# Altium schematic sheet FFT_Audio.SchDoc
size A; Organization: Altium Limited; Address1: L3, 12a Rodborough Rd; Address2: Frenchs Forest; Address3: NSW; Address4: Australia 2086; DocumentNumber: 1; SheetNumber: 1; SheetTotal: 1
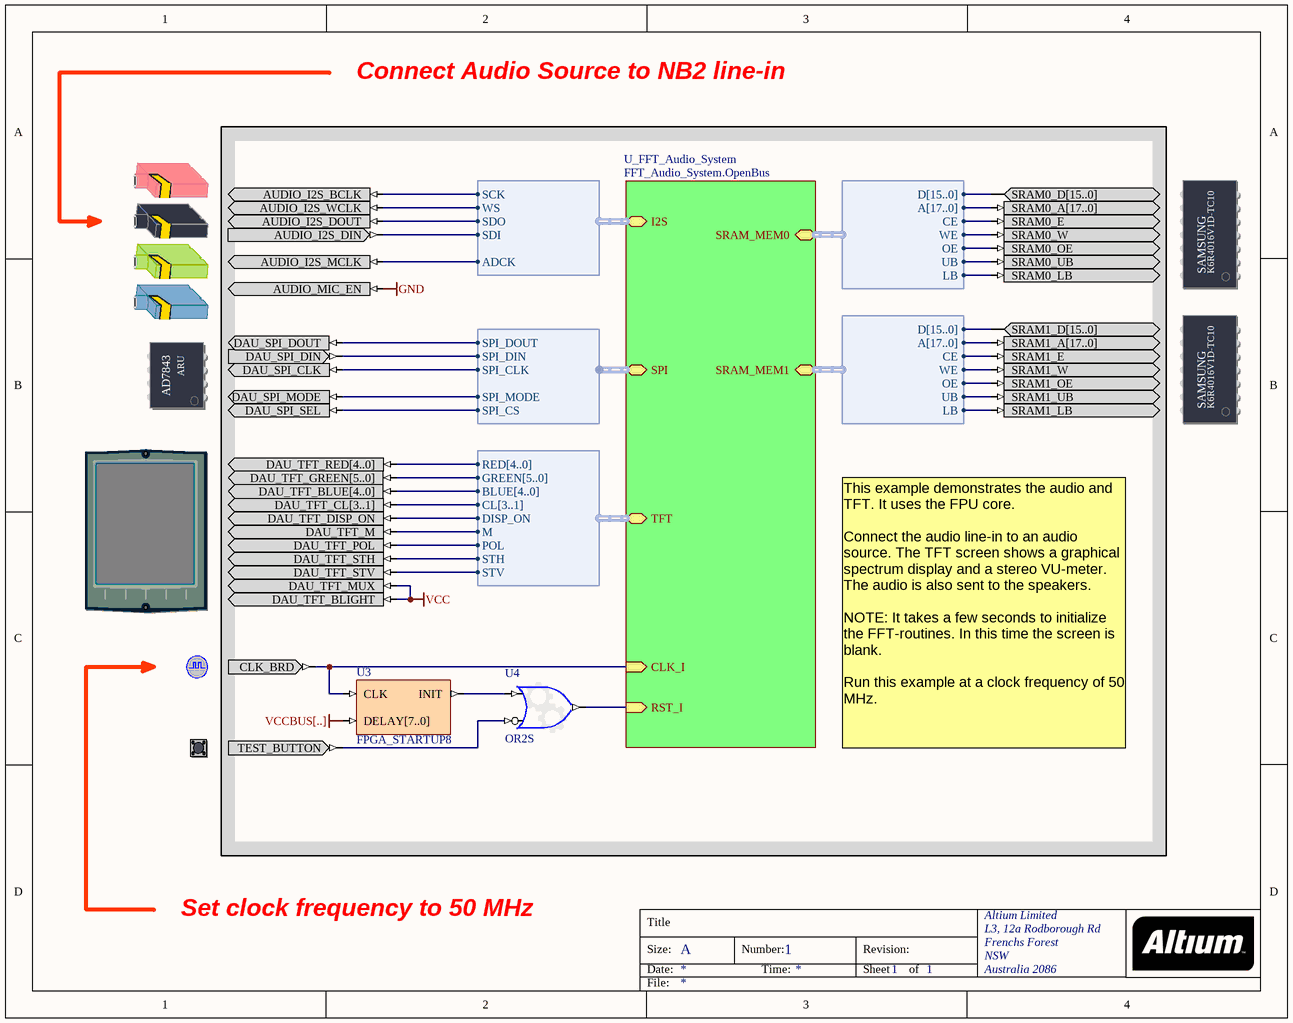
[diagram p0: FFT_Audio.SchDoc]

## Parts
(Parts that share a designator on the sheet are numbered #1, #2 ... from top to bottom, then left to right.)
?#1  AUDIO_CODEC  (value not drawn)
?#2  SRAM_DAUGHTER0  (value not drawn)
?#3  SRAM_DAUGHTER1  (value not drawn)
?#4  TOUCH_SCREEN_DIGITIZER  (value not drawn)
?#5  TFT_LCD  (value not drawn)
?#6  CLOCK_BOARD  (value not drawn)
?#7  TEST_BUTTON  (value not drawn)
U3  FPGA_STARTUP8
U4  OR2S

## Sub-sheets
U_FFT_Audio_System = FFT_Audio_System.OpenBus: RST_I (in), CLK_I (in), SPI (harness SPI_W_NB), I2S (harness I2S_W_Both), TFT (harness VGA32_TFT), SRAM_MEM0 (harness WB_MEM_CTRL_SRAM16_A18), SRAM_MEM1 (harness WB_MEM_CTRL_SRAM16_A18)

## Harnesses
VGA32_TFT: RED[4..0], GREEN[5..0], BLUE[4..0], CL[3..1], DISP_ON, M, POL, STH, STV
WB_MEM_CTRL_SRAM16_A18: D[15..0], A[17..0], CE, WE, OE, UB, LB
I2S_W_Both: SCK, WS, SDO, SDI, ADCK
SPI_W_NB: SPI_DOUT, SPI_DIN, SPI_CLK, SPI_MODE, SPI_CS

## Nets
GND: ?#1.AUDIO_MIC_EN
VCC: ?#5.DAU_TFT_BLIGHT ?#5.DAU_TFT_MUX
VCCBUS[..]: U3.DELAY[7..0]
Net?#1_AUDIO_I2S_BCLK: ?#1.AUDIO_I2S_BCLK ; sheet U_FFT_Audio_System/I2S.SCK
Net?#1_AUDIO_I2S_DIN: ?#1.AUDIO_I2S_DIN ; sheet U_FFT_Audio_System/I2S.SDI
Net?#1_AUDIO_I2S_DOUT: ?#1.AUDIO_I2S_DOUT ; sheet U_FFT_Audio_System/I2S.SDO
Net?#1_AUDIO_I2S_MCLK: ?#1.AUDIO_I2S_MCLK ; sheet U_FFT_Audio_System/I2S.ADCK
Net?#1_AUDIO_I2S_WCLK: ?#1.AUDIO_I2S_WCLK ; sheet U_FFT_Audio_System/I2S.WS
Net?#2_SRAM0_E: ?#2.SRAM0_E ; sheet U_FFT_Audio_System/SRAM_MEM0.CE
Net?#2_SRAM0_LB: ?#2.SRAM0_LB ; sheet U_FFT_Audio_System/SRAM_MEM0.LB
Net?#2_SRAM0_OE: ?#2.SRAM0_OE ; sheet U_FFT_Audio_System/SRAM_MEM0.OE
Net?#2_SRAM0_UB: ?#2.SRAM0_UB ; sheet U_FFT_Audio_System/SRAM_MEM0.UB
Net?#2_SRAM0_W: ?#2.SRAM0_W ; sheet U_FFT_Audio_System/SRAM_MEM0.WE
Net?#3_SRAM1_E: ?#3.SRAM1_E ; sheet U_FFT_Audio_System/SRAM_MEM1.CE
Net?#3_SRAM1_LB: ?#3.SRAM1_LB ; sheet U_FFT_Audio_System/SRAM_MEM1.LB
Net?#3_SRAM1_OE: ?#3.SRAM1_OE ; sheet U_FFT_Audio_System/SRAM_MEM1.OE
Net?#3_SRAM1_UB: ?#3.SRAM1_UB ; sheet U_FFT_Audio_System/SRAM_MEM1.UB
Net?#3_SRAM1_W: ?#3.SRAM1_W ; sheet U_FFT_Audio_System/SRAM_MEM1.WE
Net?#4_DAU_SPI_CLK: ?#4.DAU_SPI_CLK ; sheet U_FFT_Audio_System/SPI.SPI_CLK
Net?#4_DAU_SPI_DIN: ?#4.DAU_SPI_DIN ; sheet U_FFT_Audio_System/SPI.SPI_DIN
Net?#4_DAU_SPI_DOUT: ?#4.DAU_SPI_DOUT ; sheet U_FFT_Audio_System/SPI.SPI_DOUT
Net?#4_DAU_SPI_MODE: ?#4.DAU_SPI_MODE ; sheet U_FFT_Audio_System/SPI.SPI_MODE
Net?#4_DAU_SPI_SEL: ?#4.DAU_SPI_SEL ; sheet U_FFT_Audio_System/SPI.SPI_CS
Net?#5_DAU_TFT_DISP_ON: ?#5.DAU_TFT_DISP_ON ; sheet U_FFT_Audio_System/TFT.DISP_ON
Net?#5_DAU_TFT_M: ?#5.DAU_TFT_M ; sheet U_FFT_Audio_System/TFT.M
Net?#5_DAU_TFT_POL: ?#5.DAU_TFT_POL ; sheet U_FFT_Audio_System/TFT.POL
Net?#5_DAU_TFT_STH: ?#5.DAU_TFT_STH ; sheet U_FFT_Audio_System/TFT.STH
Net?#5_DAU_TFT_STV: ?#5.DAU_TFT_STV ; sheet U_FFT_Audio_System/TFT.STV
Net?#6_CLK_BRD: ?#6.CLK_BRD U3.CLK ; sheet U_FFT_Audio_System/CLK_I
Net?#7_TEST_BUTTON: ?#7.TEST_BUTTON U4.I1
NetU3_INIT: U3.INIT U4.I0
NetU4_O: U4.O ; sheet U_FFT_Audio_System/RST_I

Not connected (* = marked no-connect by the designer): ?#2 SRAM0_A[17..0] SRAM0_D[15..0]; ?#3 SRAM1_A[17..0] SRAM1_D[15..0]; ?#5 DAU_TFT_BLUE[4..0] DAU_TFT_CL[3..1] DAU_TFT_GREEN[5..0] DAU_TFT_RED[4..0]

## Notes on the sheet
- Connect Audio Source to NB2 line-in
- This example demonstrates the audio and TFT. It uses the FPU core.
  Connect the audio line-in to an audio source. The TFT screen shows a graphical spectrum display and a stereo VU-meter. The audio is also sent to the speakers.
  NOTE: It takes a few seconds to initialize the FFT-routines. In this time the screen is blank.
  Run this example at a clock frequency of 50 MHz.
- Set clock frequency to 50 MHz

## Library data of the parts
?#1 = AUDIO_CODEC: Audio Codec; PortComponent: True; IncludeInDSF: AUDIO_CS4270
?#2 = SRAM_DAUGHTER0: Free Static RAM - Daughterboard; PortComponent: True
?#3 = SRAM_DAUGHTER1: Free Static RAM - Daughterboard; PortComponent: True
?#4 = TOUCH_SCREEN_DIGITIZER: Touch Screen Digitizer; PortComponent: True
?#5 = TFT_LCD: TFT LCD Panel; PortComponent: True
?#6 = CLOCK_BOARD: Global System Clock Supply; PortComponent: True
?#7 = TEST_BUTTON: Test / Reset Button; PortComponent: True
U3 = FPGA_STARTUP8: FPGA Startup With 8 Bit Delay
U4 = GATE: Configurable Generic Gate; ConfiguratorName: GENERIC_GATE; ConfigurationParameters: {}Version[1.0]{}GateKind[OR]{}BusInput[False]{}GateInputType[Bit]{}GateOutputOption[Normal]{}BusWidth[8]{}RegisterOutputs[False]{}NegativeClockEdge[False]{}InputCount[2]{}InputInvert0[False]{}InputInvert1[True]{}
